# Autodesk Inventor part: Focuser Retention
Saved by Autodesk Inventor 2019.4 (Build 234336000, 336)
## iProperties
Created: 2020-09
Part Number: Focuser Retention
Material: Generic
Document SubType Name: Modeling
Designer: Administrator
Density: 1 g/cm^3
Appearance: Default
Title: Focuser Retention
Author: Administrator
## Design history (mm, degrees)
feature "Body1"
body "Solid1"
